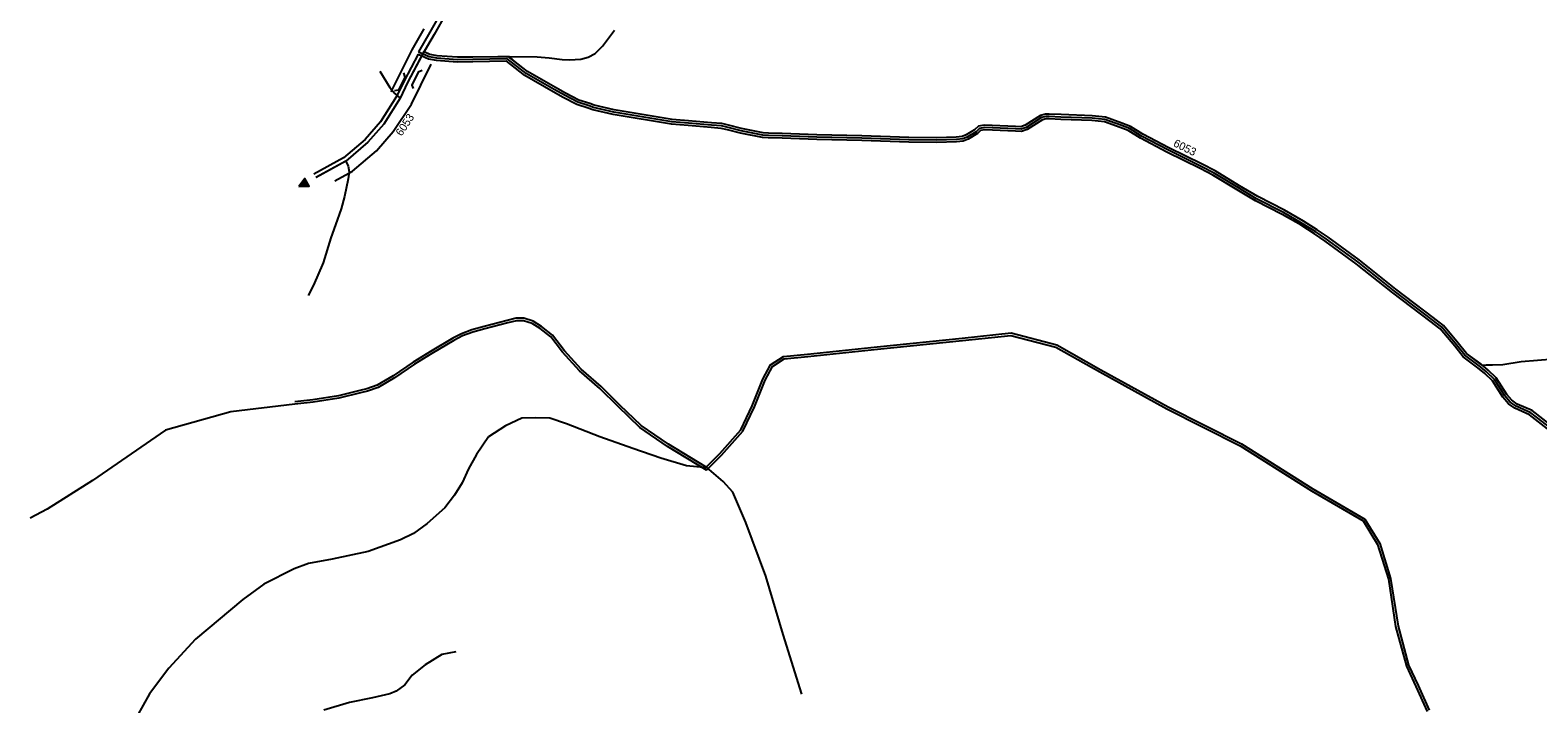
# Model space of a CAD drawing. Extents: x -547395 to -536032, y -1096268 to -1086572.
# Drawn here: x -547233 to -545330, y -1094866 to -1094015 of the extents above; entities that cross this region are included whole.
import ezdxf

# ---------------------------------------------------------------- set-up
doc = ezdxf.new("R2010")
doc.units = 0
for name, color, linetype in [('Vrstva 12', 7, 'Continuous'), ('Vrstva 5', 7, 'Continuous'), ('Vrstva 66', 7, 'Continuous'), ('Vrstva 70', 7, 'Continuous'), ('Vrstva 73', 7, 'Continuous'), ('Vrstva 75', 7, 'Continuous')]:
    doc.layers.add(name, color=color, linetype=linetype)

msp = doc.modelspace()

# ---------------------------------------------------------------- linework, layer by layer
at = {"layer": 'Vrstva 12'}
for points in [[(-546735.9, -1094042.4), (-546728.7, -1094045.6), (-546719.7, -1094047.1), (-546693.6, -1094049.1), (-546674.5, -1094048.9), (-546643, -1094048.3), (-546628.6, -1094048.6), (-546593, -1094049), (-546577.9, -1094050.2), (-546561.8, -1094052.1), (-546552.4, -1094052.6), (-546537.9, -1094051.9), (-546528.8, -1094049.5), (-546519.9, -1094044.6), (-546510.6, -1094035.6), (-546495.6, -1094015.2)], [(-545310.3, -1094516.5), (-545337.2, -1094495.5), (-545355.9, -1094487.2), (-545362.8, -1094482.4), (-545369, -1094475), (-545382.4, -1094454.2), (-545392.8, -1094444.3), (-545402, -1094436.6), (-545419.9, -1094423.2), (-545430.3, -1094410.4), (-545449, -1094388.1), (-545462.1, -1094377.9), (-545509.1, -1094342.2), (-545555.5, -1094305.3), (-545594.8, -1094276.7), (-545608.5, -1094267.2), (-545625.7, -1094256.5), (-545649.7, -1094242.6), (-545683.6, -1094225.4), (-545706.5, -1094211.7), (-545737.1, -1094192.9), (-545753.5, -1094184.6), (-545795.7, -1094163.8), (-545828.7, -1094146.5), (-545844.2, -1094136.7), (-545855.2, -1094132.5), (-545875.7, -1094125.1), (-545892.5, -1094123.4), (-545931.8, -1094121.9), (-545946.7, -1094121.3), (-545951.4, -1094121.3), (-545957.7, -1094122.8), (-545977, -1094135.3), (-545982.7, -1094137.1), (-545989.2, -1094136.8), (-546028.4, -1094135), (-546036.2, -1094136.5), (-546040.9, -1094141), (-546051.7, -1094147.5), (-546056.7, -1094149.6), (-546064.2, -1094150.2), (-546088.5, -1094151.1), (-546123.8, -1094150.7), (-546183.3, -1094148.6), (-546240.1, -1094147.4), (-546283.8, -1094145.6), (-546301.1, -1094145.3), (-546307.9, -1094144.7), (-546335.1, -1094139.5), (-546351.5, -1094135), (-546360.1, -1094133.2), (-546372.9, -1094132.1), (-546402.1, -1094129.7), (-546422.9, -1094127.9), (-546496, -1094115.7), (-546521.3, -1094110), (-546526.7, -1094107.9), (-546540.7, -1094103.5), (-546557.3, -1094094.9), (-546570.1, -1094087.7), (-546605.4, -1094067.6), (-546623.2, -1094053.6), (-546628.6, -1094048.6)], [(-546791.7, -1094067.2), (-546779.2, -1094087.7), (-546773, -1094095.1), (-546766.3, -1094101.2)], [(-546834.9, -1094180.7), (-546831.6, -1094187), (-546830.7, -1094194.1), (-546831.9, -1094202.8), (-546836.6, -1094225.4), (-546840.5, -1094240.9), (-546847.6, -1094260.8), (-546853.6, -1094277.5), (-546863.5, -1094308.9), (-546875.7, -1094337.2), (-546882.3, -1094350.3)], [(-546258.9, -1094853.4), (-546282.7, -1094777.9), (-546304.5, -1094704.4), (-546329.9, -1094636.7), (-546346.3, -1094598.6), (-546358.5, -1094585), (-546378.9, -1094567.3), (-546427.2, -1094538), (-546461.8, -1094514.2), (-546489, -1094488.4), (-546512.2, -1094465.2), (-546537.7, -1094443.1), (-546558.7, -1094420), (-546573.7, -1094400.3), (-546587.8, -1094389.5), (-546598.3, -1094382.7), (-546609.9, -1094379), (-546619.8, -1094379), (-546631, -1094381.7), (-546660.2, -1094389.5), (-546675.5, -1094393.6), (-546688.8, -1094398.4), (-546699.6, -1094404.2), (-546727.8, -1094420.8), (-546749.6, -1094434.4), (-546774.9, -1094451.6), (-546795, -1094463.5), (-546808.2, -1094468), (-546817.1, -1094470.3), (-546843.9, -1094476.8), (-546876.2, -1094481.9), (-546899.3, -1094484.3)], [(-546380.7, -1094567.5), (-546362.5, -1094549.5), (-546336, -1094519.6), (-546321.7, -1094489.6), (-546308.1, -1094455.6), (-546298.6, -1094437.9), (-546282.3, -1094427.1), (-546251.7, -1094424.3), (-546163.9, -1094414.8), (-546056.5, -1094403.9), (-545995, -1094397.5), (-545937.1, -1094412.4), (-545881.6, -1094444.1), (-545796.7, -1094490.7), (-545704.2, -1094537.4), (-545614, -1094594.1), (-545548.3, -1094632.4), (-545529.4, -1094663.2), (-545515.7, -1094707.4), (-545506.4, -1094767.5), (-545493, -1094816.8), (-545481.1, -1094842.5), (-545466.9, -1094873.8)], [(-545309.9, -1094430.7), (-545351.1, -1094434), (-545373.9, -1094437.5), (-545388.3, -1094438), (-545395.2, -1094438.1), (-545399.8, -1094438.5)], [(-546378.4, -1094567.7), (-546404.6, -1094565.1), (-546437.2, -1094555.6), (-546472.2, -1094543.3), (-546514, -1094528.4), (-546556.2, -1094512), (-546577.3, -1094505.2), (-546594.9, -1094504.5), (-546612.6, -1094505.2), (-546633, -1094514.7), (-546654.8, -1094528.4), (-546669.7, -1094550.8), (-546679.8, -1094569), (-546687.9, -1094586.7), (-546697.4, -1094602), (-546709.7, -1094618), (-546732.1, -1094638.1), (-546749.4, -1094650.7), (-546765.8, -1094658.5), (-546806.7, -1094673.3), (-546851.9, -1094682.8), (-546881.8, -1094688.6), (-546899.9, -1094695.1), (-546938.1, -1094714.6), (-546964.6, -1094734), (-547024.4, -1094784), (-547058.1, -1094820.4), (-547082.6, -1094853.1), (-547106.4, -1094895.9)], [(-546695.7, -1094800), (-546713.4, -1094803.4), (-546734.5, -1094816.3), (-546750.8, -1094829.3), (-546760.3, -1094841.5), (-546771.2, -1094849.7), (-546779.3, -1094853.1), (-546801.1, -1094857.9), (-546830.3, -1094864), (-546862.3, -1094873.5)]]:
    msp.add_lwpolyline(points, dxfattribs=at)
at = {"layer": 'Vrstva 5'}
msp.add_lwpolyline([(-546708.4, -1093994.6), (-546723.3, -1094020.8), (-546738.8, -1094047.3), (-546756.8, -1094081.5), (-546766.3, -1094101.3), (-546786.9, -1094133.9), (-546806.8, -1094156.8), (-546834.8, -1094180.6), (-546872.2, -1094201.1)], dxfattribs=at)
for points in [[(-546894.1, -1094212.8), (-546881.2, -1094212.3), (-546886.4, -1094202.4)], [(-546892.4, -1094211.9), (-546882.5, -1094211.6), (-546886.5, -1094203.9)], [(-546890.8, -1094211), (-546883.8, -1094210.8), (-546886.7, -1094205.4)], [(-546889.2, -1094210.2), (-546885.1, -1094210), (-546886.8, -1094206.9)], [(-546887.6, -1094209.3), (-546886.4, -1094209.3), (-546886.9, -1094208.4)]]:
    msp.add_lwpolyline(points, close=True, dxfattribs=at)
at = {"layer": 'Vrstva 66'}
for points in [[(-546736.3, -1094013.4), (-546751.4, -1094040), (-546767, -1094071.3), (-546777.8, -1094093.3)], [(-546848.6, -1094205.3), (-546826.2, -1094193.1), (-546796.2, -1094167.5), (-546775, -1094143), (-546751.9, -1094108.7), (-546740.1, -1094084.6), (-546726.9, -1094058.2)]]:
    msp.add_lwpolyline(points, dxfattribs=at)
at = {"layer": 'Vrstva 70'}
for points in [[(-546641.5, -1093857.8), (-546632.9, -1093880.8), (-546659.7, -1093916.1), (-546713.5, -1093991.4), (-546728.5, -1094017.8), (-546743, -1094042.6)], [(-546743.6, -1094045.6), (-546761.2, -1094079.2), (-546770.7, -1094098.9), (-546790.9, -1094130.9), (-546810.3, -1094153.3), (-546837.6, -1094176.5), (-546875.1, -1094196.9)], [(-546743.6, -1094045.6), (-546730.4, -1094051.4), (-546720.5, -1094053), (-546693.7, -1094055.2), (-546674.4, -1094054.8), (-546632.4, -1094054.1)], [(-546743, -1094042.6), (-546729.5, -1094048.5), (-546720.1, -1094050.1), (-546693.6, -1094052.2), (-546674.5, -1094051.8), (-546631.3, -1094051)], [(-545313.8, -1094521.4), (-545340.3, -1094500.7), (-545358.9, -1094492.5), (-545366.9, -1094486.9), (-545373.9, -1094478.6), (-545387.1, -1094458), (-545396.8, -1094448.8), (-545405.8, -1094441.3), (-545424.1, -1094427.6), (-545434.9, -1094414.2), (-545453.2, -1094392.4), (-545465.8, -1094382.7), (-545512.8, -1094347), (-545559.1, -1094310.1), (-545598.3, -1094281.6), (-545611.8, -1094272.2), (-545628.8, -1094261.6), (-545652.5, -1094247.9), (-545686.5, -1094230.6), (-545709.6, -1094216.8), (-545740, -1094198.2), (-545756.1, -1094190), (-545798.4, -1094169.1), (-545831.7, -1094151.7), (-545846.9, -1094142.1), (-545857.3, -1094138.1), (-545877.1, -1094131), (-545892.9, -1094129.4), (-545932, -1094127.9), (-545946.8, -1094127.3), (-545950.7, -1094127.3), (-545955.3, -1094128.4), (-545974.4, -1094140.8), (-545981.9, -1094143.2), (-545989.5, -1094142.8), (-546028, -1094141.1), (-546033.4, -1094142.1), (-546037.3, -1094145.8), (-546048.9, -1094152.9), (-546055.3, -1094155.5), (-546063.8, -1094156.2), (-546088.5, -1094157.1), (-546123.9, -1094156.7), (-546183.4, -1094154.6), (-546240.3, -1094153.4), (-546284, -1094151.6), (-546301.4, -1094151.3), (-546308.7, -1094150.7), (-546336.5, -1094145.3), (-546352.9, -1094140.9), (-546361, -1094139.2), (-546373.4, -1094138), (-546402.6, -1094135.7), (-546423.6, -1094133.8), (-546497.2, -1094121.6), (-546523.1, -1094115.8), (-546528.7, -1094113.6), (-546543, -1094109), (-546560.2, -1094100.1), (-546573.1, -1094092.9), (-546608.7, -1094072.6), (-546632.4, -1094054.1)], [(-545312, -1094519), (-545338.7, -1094498.1), (-545357.4, -1094489.8), (-545364.8, -1094484.7), (-545371.4, -1094476.8), (-545384.7, -1094456.1), (-545394.8, -1094446.6), (-545403.9, -1094439), (-545422, -1094425.4), (-545432.6, -1094412.3), (-545451.1, -1094390.2), (-545463.9, -1094380.3), (-545511, -1094344.6), (-545557.3, -1094307.7), (-545596.5, -1094279.2), (-545610.1, -1094269.7), (-545627.3, -1094259.1), (-545651.1, -1094245.3), (-545685, -1094228), (-545708, -1094214.3), (-545738.6, -1094195.6), (-545754.8, -1094187.3), (-545797.1, -1094166.4), (-545830.2, -1094149.1), (-545845.5, -1094139.4), (-545856.2, -1094135.3), (-545876.4, -1094128), (-545892.7, -1094126.4), (-545931.9, -1094124.9), (-545946.7, -1094124.3), (-545951.1, -1094124.3), (-545956.5, -1094125.6), (-545975.7, -1094138.1), (-545982.3, -1094140.1), (-545989.3, -1094139.8), (-546028.2, -1094138.1), (-546034.8, -1094139.3), (-546039.1, -1094143.4), (-546050.3, -1094150.2), (-546056, -1094152.6), (-546064, -1094153.2), (-546088.5, -1094154.1), (-546123.9, -1094153.7), (-546183.4, -1094151.6), (-546240.2, -1094150.4), (-546283.9, -1094148.6), (-546301.2, -1094148.3), (-546308.3, -1094147.7), (-546335.8, -1094142.4), (-546352.2, -1094138), (-546360.6, -1094136.2), (-546373.2, -1094135), (-546402.3, -1094132.7), (-546423.2, -1094130.9), (-546496.6, -1094118.6), (-546522.2, -1094112.9), (-546527.7, -1094110.8), (-546541.8, -1094106.3), (-546558.7, -1094097.5), (-546571.6, -1094090.3), (-546607, -1094070.1), (-546631.3, -1094051)], [(-546379.5, -1094570.5), (-546428.8, -1094540.6), (-546463.7, -1094516.6), (-546491.1, -1094490.5), (-546514.2, -1094467.4), (-546539.8, -1094445.3), (-546561, -1094421.9), (-546575.8, -1094402.4), (-546589.5, -1094392), (-546599.6, -1094385.5), (-546610.4, -1094382), (-546619.4, -1094382), (-546630.2, -1094384.6), (-546659.4, -1094392.4), (-546674.6, -1094396.5), (-546687.5, -1094401.1), (-546698.2, -1094406.8), (-546726.3, -1094423.4), (-546748, -1094437), (-546773.3, -1094454.2), (-546793.7, -1094466.3), (-546807.4, -1094470.8), (-546816.3, -1094473.2), (-546843.4, -1094479.8), (-546875.9, -1094484.9), (-546899, -1094487.3), (-546980.1, -1094497.1), (-547062.4, -1094520.1), (-547154.6, -1094583.7), (-547211.6, -1094619.9), (-547233.3, -1094631.4)], [(-546379.5, -1094570.5), (-546360.3, -1094551.6), (-546333.5, -1094521.3), (-546319, -1094490.9), (-546305.4, -1094456.9), (-546296.3, -1094440), (-546281.2, -1094430), (-546251.4, -1094427.3), (-546163.6, -1094417.8), (-546056.2, -1094406.9), (-545995.3, -1094400.5), (-545938.2, -1094415.2), (-545883, -1094446.7), (-545798.1, -1094493.4), (-545705.6, -1094540), (-545615.5, -1094596.7), (-545550.4, -1094634.6), (-545532.2, -1094664.4), (-545518.6, -1094708.1), (-545509.4, -1094768.1), (-545495.8, -1094817.9), (-545483.8, -1094843.8), (-545469.5, -1094875.2)]]:
    msp.add_lwpolyline(points, dxfattribs=at)
at = {"layer": 'Vrstva 73'}
for points in [[(-546736.2, -1094042.3), (-546756.8, -1094081.5), (-546766.3, -1094101.3), (-546786.9, -1094133.9), (-546806.8, -1094156.8), (-546834.8, -1094180.6), (-546872.4, -1094201.1)], [(-546736.2, -1094042.3), (-546728.7, -1094045.6), (-546719.7, -1094047.1), (-546693.6, -1094049.1), (-546674.5, -1094048.9), (-546643, -1094048.3), (-546629.7, -1094048.5)], [(-545399.6, -1094438.4), (-545419.9, -1094423.2), (-545430.3, -1094410.4), (-545449, -1094388.1), (-545462.1, -1094377.9), (-545509.1, -1094342.2), (-545555.5, -1094305.3), (-545594.8, -1094276.7), (-545608.5, -1094267.2), (-545625.7, -1094256.5), (-545649.7, -1094242.6), (-545683.6, -1094225.4), (-545706.5, -1094211.7), (-545737.1, -1094192.9), (-545753.5, -1094184.6), (-545795.7, -1094163.8), (-545828.7, -1094146.5), (-545844.2, -1094136.7), (-545855.2, -1094132.5), (-545875.7, -1094125.1), (-545892.5, -1094123.4), (-545931.8, -1094121.9), (-545946.7, -1094121.3), (-545951.4, -1094121.3), (-545957.7, -1094122.8), (-545977, -1094135.3), (-545982.7, -1094137.1), (-545989.2, -1094136.8), (-546028.4, -1094135), (-546036.2, -1094136.5), (-546040.9, -1094141), (-546051.7, -1094147.5), (-546056.7, -1094149.6), (-546064.2, -1094150.2), (-546088.5, -1094151.1), (-546123.8, -1094150.7), (-546183.3, -1094148.6), (-546240.1, -1094147.4), (-546283.8, -1094145.6), (-546301.1, -1094145.3), (-546307.9, -1094144.7), (-546335.1, -1094139.5), (-546351.5, -1094135), (-546360.1, -1094133.2), (-546372.9, -1094132.1), (-546402.1, -1094129.7), (-546422.9, -1094127.9), (-546496, -1094115.7), (-546521.3, -1094110), (-546526.7, -1094107.9), (-546540.7, -1094103.5), (-546557.3, -1094094.9), (-546570.1, -1094087.7), (-546605.4, -1094067.6), (-546629.7, -1094048.5)], [(-545309.9, -1094430.7), (-545351.1, -1094434), (-545373.9, -1094437.5), (-545399.6, -1094438.4)]]:
    msp.add_lwpolyline(points, dxfattribs=at)
at = {"layer": 'Vrstva 75'}
for points in [[(-546738.5, -1094066.2), (-546743.5, -1094068.1), (-546751.5, -1094084.5), (-546749.9, -1094089.1)], [(-546761.9, -1094069.3), (-546760.4, -1094074.4), (-546768.4, -1094090.8), (-546773.2, -1094091.7)]]:
    msp.add_lwpolyline(points, dxfattribs=at)

# ---------------------------------------------------------------- texts
at = {"layer": 'Vrstva 5'}
msp.add_text('6053', height=10, rotation=56.4221, dxfattribs=at).set_placement((-546764.3, -1094149.8))
at = {"layer": 'Vrstva 73'}
msp.add_text('6053', height=10, rotation=333.7396, dxfattribs=at).set_placement((-545790.9, -1094161.3))

doc.saveas('drawing.dxf')
